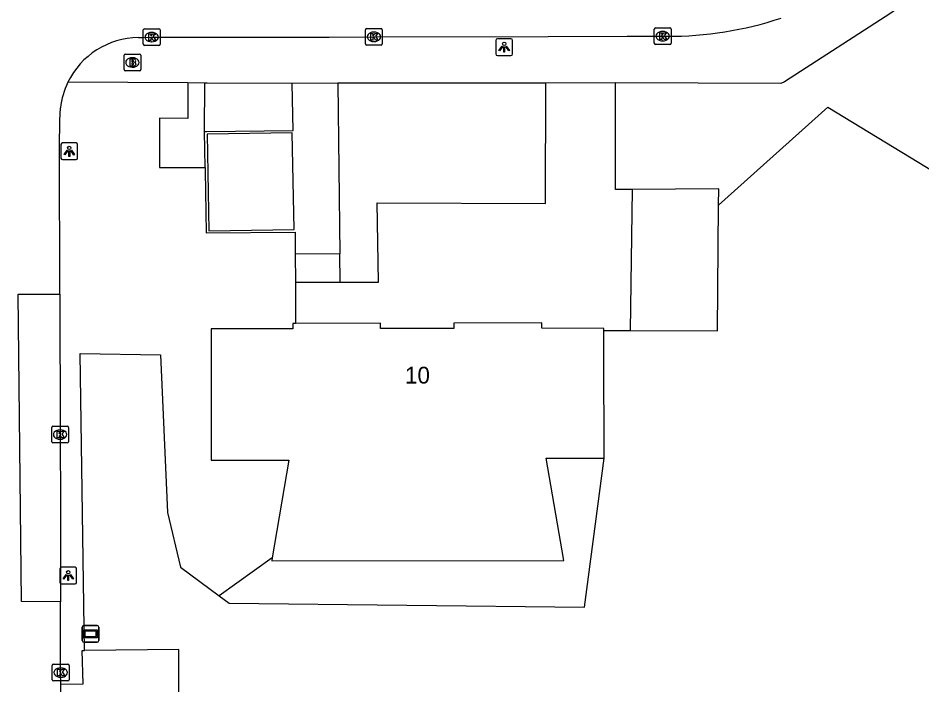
# Model space of a CAD drawing. Extents: x 161477 to 163040, y 383680 to 384868.
# Drawn here: x 162381.9 to 162435.8, y 384132.8 to 384172.5 of the extents above; entities that cross this region are included whole.
import ezdxf

# ---------------------------------------------------------------- set-up
doc = ezdxf.new("R2010")
doc.units = 0
for name, color, linetype in [('IMGEO_Brandkraan', 7, 'Continuous'), ('IMGEO_Groenvoorziening', 7, 'Continuous'), ('IMGEO_Kolk', 7, 'Continuous'), ('IMGEO_Lichtpunt', 7, 'Continuous'), ('IMGEO_Pand', 7, 'Continuous'), ('IMGEO_Pand_nummerreeks', 7, 'Continuous'), ('IMGEO_Parkeervlak_open', 7, 'Continuous'), ('IMGEO_Rijbaan_lokaal_open', 7, 'Continuous'), ('IMGEO_Verklikker', 7, 'Continuous'), ('IMGEO_Voetpad_open', 7, 'Continuous')]:
    doc.layers.add(name, color=color, linetype=linetype)

msp = doc.modelspace()

# ---------------------------------------------------------------- linework, layer by layer
at = {"layer": 'IMGEO_Brandkraan'}
for p, q in [((162388.314, 384170.36), (162389.166, 384170.36)), ((162388.239, 384169.434), (162388.239, 384170.286)), ((162388.727, 384170.14), (162388.752, 384170.14)), ((162389.24, 384170.286), (162389.24, 384169.434)), ((162389.166, 384169.36), (162388.314, 384169.36)), ((162388.75, 384169.58), (162388.725, 384169.58))]:
    msp.add_line(p, q, dxfattribs=at)
for points in [[(162388.314, 384170.36), (162389.166, 384170.36)], [(162388.239, 384169.434), (162388.239, 384170.286)], [(162388.587, 384170.06), (162388.587, 384169.66), (162388.8, 384169.66)], [(162388.818, 384170.06), (162388.587, 384170.06)], [(162388.766, 384169.979), (162388.712, 384169.979), (162388.712, 384169.903)], [(162388.712, 384169.903), (162388.765, 384169.903)], [(162388.774, 384169.827), (162388.712, 384169.827), (162388.712, 384169.746)], [(162389.24, 384170.286), (162389.24, 384169.434)], [(162389.166, 384169.36), (162388.314, 384169.36)], [(162388.712, 384169.746), (162388.774, 384169.746)]]:
    msp.add_lwpolyline(points, dxfattribs=at)
for centre, radius, start, end in [((162388.316, 384170.284), 0.0765, 91.552, 178.448), ((162388.316, 384170.284), 0.0765, 91.552, 178.448), ((162389.164, 384170.284), 0.0765, 1.552, 88.448), ((162389.164, 384170.284), 0.0765, 1.552, 88.448), ((162388.767, 384169.941), 0.0379, 267.8285, 90.9355), ((162388.775, 384169.786), 0.0404, 269.8759, 90.5077), ((162388.822, 384169.915), 0.145, 59.4692, 91.5367), ((162388.847, 384169.962), 0.0922, 285.5137, 58.1501), ((162388.852, 384169.77), 0.105, 301.3115, 78.989), ((162388.316, 384169.436), 0.0765, 181.552, 268.448), ((162388.316, 384169.436), 0.0765, 181.552, 268.448), ((162388.806, 384169.911), 0.251, 268.6676, 293.5347), ((162389.164, 384169.436), 0.0765, 271.552, 358.448), ((162389.164, 384169.436), 0.0765, 271.552, 358.448)]:
    msp.add_arc(centre, radius, start, end, dxfattribs=at)
for centre, major_axis, ratio, start_param, end_param in [((162388.726, 384169.86), (-0.387, 0.002), 0.722429, 4.712389, 7.853982), ((162388.751, 384169.86), (-0.39, 0.002), 0.717154, 1.570796, 4.712389)]:
    msp.add_ellipse(centre, major_axis=major_axis, ratio=ratio, start_param=start_param, end_param=end_param, dxfattribs=at)
at = {"layer": 'IMGEO_Groenvoorziening'}
for points in [[(162423.686, 384161.363), (162430.2, 384167.193), (162450.329, 384154.952)], [(162385.887, 384134.817), (162385.626, 384152.513), (162390.407, 384152.435), (162390.839, 384143.031), (162391.599, 384139.791), (162393.903, 384138.082)], [(162393.903, 384138.082), (162394.498, 384137.641), (162415.691, 384137.403), (162416.87, 384146.287)], [(162397.075, 384140.334), (162393.903, 384138.082)]]:
    msp.add_lwpolyline(points, dxfattribs=at)
at = {"layer": 'IMGEO_Kolk'}
for p, q in [((162419.927, 384171.928), (162420.779, 384171.928)), ((162389.389, 384170.946), (162389.389, 384171.798)), ((162389.464, 384171.872), (162390.316, 384171.872)), ((162389.877, 384171.652), (162389.902, 384171.652)), ((162390.39, 384171.798), (162390.39, 384170.946)), ((162402.634, 384170.962), (162402.634, 384171.814)), ((162402.709, 384171.888), (162403.561, 384171.888)), ((162403.122, 384171.668), (162403.147, 384171.668)), ((162403.635, 384171.814), (162403.635, 384170.962)), ((162419.852, 384171.002), (162419.852, 384171.854)), ((162420.34, 384171.708), (162420.365, 384171.708)), ((162420.853, 384171.854), (162420.853, 384171.002)), ((162390.316, 384170.872), (162389.464, 384170.872)), ((162389.9, 384171.092), (162389.875, 384171.092)), ((162403.561, 384170.888), (162402.709, 384170.888)), ((162403.145, 384171.108), (162403.12, 384171.108)), ((162420.779, 384170.928), (162419.927, 384170.928)), ((162420.363, 384171.148), (162420.338, 384171.148)), ((162383.929, 384147.258), (162383.929, 384148.11)), ((162384.004, 384148.184), (162384.856, 384148.184)), ((162384.417, 384147.964), (162384.442, 384147.964)), ((162384.93, 384148.11), (162384.93, 384147.258)), ((162384.856, 384147.184), (162384.004, 384147.184)), ((162384.44, 384147.404), (162384.415, 384147.404)), ((162383.96, 384133.074), (162383.96, 384133.926)), ((162384.035, 384134), (162384.887, 384134)), ((162384.448, 384133.78), (162384.473, 384133.78)), ((162384.961, 384133.926), (162384.961, 384133.074)), ((162384.471, 384133.22), (162384.446, 384133.22)), ((162384.887, 384133), (162384.035, 384133))]:
    msp.add_line(p, q, dxfattribs=at)
for points in [[(162419.927, 384171.928), (162420.779, 384171.928)], [(162389.389, 384170.946), (162389.389, 384171.798)], [(162389.464, 384171.872), (162390.316, 384171.872)], [(162389.71, 384171.572), (162389.833, 384171.572), (162389.833, 384171.421), (162389.963, 384171.572), (162390.127, 384171.572), (162389.981, 384171.421), (162390.134, 384171.172), (162389.982, 384171.172), (162389.897, 384171.336), (162389.833, 384171.269), (162389.833, 384171.172), (162389.71, 384171.172), (162389.71, 384171.572)], [(162390.39, 384171.798), (162390.39, 384170.946)], [(162402.634, 384170.962), (162402.634, 384171.814)], [(162402.709, 384171.888), (162403.561, 384171.888)], [(162402.955, 384171.588), (162403.078, 384171.588), (162403.078, 384171.437), (162403.208, 384171.588), (162403.372, 384171.588), (162403.226, 384171.437), (162403.379, 384171.188), (162403.227, 384171.188), (162403.142, 384171.352), (162403.078, 384171.285), (162403.078, 384171.188), (162402.955, 384171.188), (162402.955, 384171.588)], [(162403.635, 384171.814), (162403.635, 384170.962)], [(162419.852, 384171.002), (162419.852, 384171.854)], [(162420.173, 384171.628), (162420.296, 384171.628), (162420.296, 384171.477), (162420.426, 384171.628), (162420.59, 384171.628), (162420.444, 384171.477), (162420.597, 384171.228), (162420.445, 384171.228), (162420.36, 384171.392), (162420.296, 384171.325), (162420.296, 384171.228), (162420.173, 384171.228), (162420.173, 384171.628)], [(162420.853, 384171.854), (162420.853, 384171.002)], [(162390.316, 384170.872), (162389.464, 384170.872)], [(162403.561, 384170.888), (162402.709, 384170.888)], [(162420.779, 384170.928), (162419.927, 384170.928)], [(162383.929, 384147.258), (162383.929, 384148.11)], [(162384.004, 384148.184), (162384.856, 384148.184)], [(162384.25, 384147.884), (162384.373, 384147.884), (162384.373, 384147.733), (162384.503, 384147.884), (162384.667, 384147.884), (162384.521, 384147.733), (162384.674, 384147.484), (162384.522, 384147.484), (162384.437, 384147.648), (162384.373, 384147.581), (162384.373, 384147.484), (162384.25, 384147.484), (162384.25, 384147.884)], [(162384.93, 384148.11), (162384.93, 384147.258)], [(162384.856, 384147.184), (162384.004, 384147.184)], [(162383.96, 384133.074), (162383.96, 384133.926)], [(162384.035, 384134), (162384.887, 384134)], [(162384.281, 384133.7), (162384.404, 384133.7), (162384.404, 384133.549), (162384.534, 384133.7), (162384.698, 384133.7), (162384.552, 384133.549), (162384.705, 384133.3), (162384.553, 384133.3), (162384.468, 384133.464), (162384.404, 384133.397), (162384.404, 384133.3), (162384.281, 384133.3), (162384.281, 384133.7)], [(162384.961, 384133.926), (162384.961, 384133.074)], [(162384.887, 384133), (162384.035, 384133)]]:
    msp.add_lwpolyline(points, dxfattribs=at)
for centre, start, end in [((162419.929, 384171.852), 91.552, 178.448), ((162419.929, 384171.852), 91.552, 178.448), ((162420.777, 384171.852), 1.552, 88.448), ((162420.777, 384171.852), 1.552, 88.448), ((162389.466, 384171.796), 91.552, 178.448), ((162389.466, 384171.796), 91.552, 178.448), ((162390.314, 384171.796), 1.552, 88.448), ((162390.314, 384171.796), 1.552, 88.448), ((162402.711, 384171.812), 91.552, 178.448), ((162402.711, 384171.812), 91.552, 178.448), ((162403.559, 384171.812), 1.552, 88.448), ((162403.559, 384171.812), 1.552, 88.448), ((162389.466, 384170.948), 181.552, 268.448), ((162389.466, 384170.948), 181.552, 268.448), ((162390.314, 384170.948), 271.552, 358.448), ((162390.314, 384170.948), 271.552, 358.448), ((162402.711, 384170.964), 181.552, 268.448), ((162402.711, 384170.964), 181.552, 268.448), ((162403.559, 384170.964), 271.552, 358.448), ((162403.559, 384170.964), 271.552, 358.448), ((162419.929, 384171.004), 181.552, 268.448), ((162419.929, 384171.004), 181.552, 268.448), ((162420.777, 384171.004), 271.552, 358.448), ((162420.777, 384171.004), 271.552, 358.448), ((162384.006, 384148.108), 91.552, 178.448), ((162384.006, 384148.108), 91.552, 178.448), ((162384.854, 384148.108), 1.552, 88.448), ((162384.854, 384148.108), 1.552, 88.448), ((162384.006, 384147.26), 181.552, 268.448), ((162384.006, 384147.26), 181.552, 268.448), ((162384.854, 384147.26), 271.552, 358.448), ((162384.854, 384147.26), 271.552, 358.448), ((162384.037, 384133.924), 91.552, 178.448), ((162384.037, 384133.924), 91.552, 178.448), ((162384.885, 384133.924), 1.552, 88.448), ((162384.885, 384133.924), 1.552, 88.448), ((162384.037, 384133.076), 181.552, 268.448), ((162384.037, 384133.076), 181.552, 268.448), ((162384.885, 384133.076), 271.552, 358.448), ((162384.885, 384133.076), 271.552, 358.448)]:
    msp.add_arc(centre, 0.0765, start, end, dxfattribs=at)
for centre, major_axis, ratio, start_param, end_param in [((162389.876, 384171.372), (-0.387, 0.002), 0.722429, 4.712389, 7.853982), ((162389.901, 384171.372), (-0.39, 0.002), 0.717154, 1.570796, 4.712389), ((162403.121, 384171.388), (-0.387, 0.002), 0.722429, 4.712389, 7.853982), ((162403.146, 384171.388), (-0.39, 0.002), 0.717154, 1.570796, 4.712389), ((162420.339, 384171.428), (-0.387, 0.002), 0.722429, 4.712389, 7.853982), ((162420.364, 384171.428), (-0.39, 0.002), 0.717154, 1.570796, 4.712389), ((162384.416, 384147.684), (-0.387, 0.002), 0.722429, 4.712389, 7.853982), ((162384.441, 384147.684), (-0.39, 0.002), 0.717154, 1.570796, 4.712389), ((162384.447, 384133.5), (-0.387, 0.002), 0.722429, 4.712389, 7.853982), ((162384.472, 384133.5), (-0.39, 0.002), 0.717154, 1.570796, 4.712389)]:
    msp.add_ellipse(centre, major_axis=major_axis, ratio=ratio, start_param=start_param, end_param=end_param, dxfattribs=at)
at = {"layer": 'IMGEO_Lichtpunt'}
for p, q in [((162410.407, 384171.173), (162410.407, 384170.366)), ((162410.407, 384171.173), (162410.407, 384170.366)), ((162411.309, 384171.268), (162410.501, 384171.268)), ((162411.309, 384171.268), (162410.501, 384171.268)), ((162411.403, 384170.366), (162411.403, 384171.173)), ((162411.403, 384170.366), (162411.403, 384171.173)), ((162410.501, 384170.272), (162411.309, 384170.272)), ((162410.501, 384170.272), (162411.309, 384170.272)), ((162384.477, 384164.972), (162384.477, 384164.165)), ((162384.477, 384164.972), (162384.477, 384164.165)), ((162385.379, 384165.067), (162384.571, 384165.067)), ((162385.379, 384165.067), (162384.571, 384165.067)), ((162385.473, 384164.165), (162385.473, 384164.972)), ((162385.473, 384164.165), (162385.473, 384164.972)), ((162384.571, 384164.071), (162385.379, 384164.071)), ((162384.571, 384164.071), (162385.379, 384164.071)), ((162384.415, 384139.685), (162384.415, 384138.878)), ((162384.415, 384139.685), (162384.415, 384138.878)), ((162385.317, 384139.78), (162384.509, 384139.78)), ((162385.317, 384139.78), (162384.509, 384139.78)), ((162385.411, 384138.878), (162385.411, 384139.685)), ((162385.411, 384138.878), (162385.411, 384139.685)), ((162384.509, 384138.784), (162385.317, 384138.784)), ((162384.509, 384138.784), (162385.317, 384138.784))]:
    msp.add_line(p, q, dxfattribs=at)
for points in [[(162410.781, 384170.837), (162410.82, 384170.809), (162410.632, 384170.547), (162410.594, 384170.574), (162410.781, 384170.837)], [(162410.883, 384170.789), (162410.93, 384170.789), (162410.93, 384170.467), (162410.883, 384170.467), (162410.883, 384170.789)], [(162410.993, 384170.809), (162411.031, 384170.836), (162411.218, 384170.574), (162411.179, 384170.546), (162410.993, 384170.809)], [(162384.851, 384164.636), (162384.89, 384164.608), (162384.702, 384164.346), (162384.664, 384164.373), (162384.851, 384164.636)], [(162384.953, 384164.588), (162385, 384164.588), (162385, 384164.266), (162384.953, 384164.266), (162384.953, 384164.588)], [(162385.063, 384164.608), (162385.101, 384164.635), (162385.288, 384164.373), (162385.249, 384164.345), (162385.063, 384164.608)], [(162384.789, 384139.349), (162384.828, 384139.321), (162384.64, 384139.059), (162384.602, 384139.086), (162384.789, 384139.349)], [(162384.891, 384139.301), (162384.938, 384139.301), (162384.938, 384138.979), (162384.891, 384138.979), (162384.891, 384139.301)], [(162385.001, 384139.321), (162385.039, 384139.348), (162385.226, 384139.086), (162385.187, 384139.058), (162385.001, 384139.321)]]:
    msp.add_lwpolyline(points, dxfattribs=at)
for centre in [(162410.906, 384170.971), (162384.976, 384164.77), (162384.914, 384139.483)]:
    msp.add_circle(centre, 0.0994, dxfattribs=at)
for centre, start, end in [((162410.501, 384171.173), 90, 180), ((162410.501, 384171.173), 90, 180), ((162411.309, 384171.173), 0, 90), ((162411.309, 384171.173), 0, 90), ((162410.501, 384170.366), 180, 270), ((162410.501, 384170.366), 180, 270), ((162411.309, 384170.366), 270, 0), ((162411.309, 384170.366), 270, 360), ((162384.571, 384164.972), 90, 180), ((162384.571, 384164.972), 90, 180), ((162385.379, 384164.972), 0, 90), ((162385.379, 384164.972), 0, 90), ((162384.571, 384164.165), 180, 270), ((162384.571, 384164.165), 180, 270), ((162385.379, 384164.165), 270, 0), ((162385.379, 384164.165), 270, 360), ((162384.509, 384139.685), 90, 180), ((162384.509, 384139.685), 90, 180), ((162385.317, 384139.685), 0, 90), ((162385.317, 384139.685), 0, 90), ((162384.509, 384138.878), 180, 270), ((162384.509, 384138.878), 180, 270), ((162385.317, 384138.878), 270, 0), ((162385.317, 384138.878), 270, 360)]:
    msp.add_arc(centre, 0.0946, start, end, dxfattribs=at)
at = {"layer": 'IMGEO_Pand'}
for points in [[(162393.304, 384159.832), (162398.375, 384159.908), (162398.265, 384165.669), (162393.194, 384165.593), (162393.304, 384159.832)], [(162398.47, 384154.313), (162398.309, 384154.313), (162398.31, 384153.993), (162393.431, 384153.979), (162393.433, 384146.157), (162398.073, 384146.158), (162397.075, 384140.334)], [(162416.837, 384153.891), (162416.837, 384154.001), (162413.142, 384154.028), (162413.141, 384154.348), (162407.9, 384154.328), (162407.901, 384154.008), (162403.537, 384154.004), (162403.536, 384154.324), (162398.47, 384154.313)], [(162416.87, 384146.287), (162416.843, 384152.651), (162416.837, 384153.891)], [(162397.075, 384140.334), (162397.045, 384140.16), (162414.456, 384140.188), (162413.41, 384146.272), (162416.87, 384146.287)]]:
    msp.add_lwpolyline(points, dxfattribs=at)
at = {"layer": 'IMGEO_Parkeervlak_open'}
for points in [[(162423.686, 384161.363), (162423.694, 384162.32), (162418.525, 384162.295)], [(162418.419, 384153.886), (162423.619, 384153.869), (162423.686, 384161.363)], [(162384.414, 384156.056), (162384.43, 384147.685), (162384.451, 384143.354), (162384.457, 384137.718)]]:
    msp.add_lwpolyline(points, dxfattribs=at)
at = {"layer": 'IMGEO_Rijbaan_lokaal_open'}
for points in [[(162389.098, 384171.347), (162389.404, 384171.346), (162389.89, 384171.373), (162398.224, 384171.366), (162400.467, 384171.373), (162403.135, 384171.389), (162413.531, 384171.412), (162418.228, 384171.418), (162420.603, 384171.425)], [(162384.414, 384156.056), (162384.398, 384164.831), (162384.403, 384166.394), (162384.445, 384167.157)], [(162384.457, 384137.718), (162382.117, 384137.738), (162381.922, 384156.051), (162384.414, 384156.056)], [(162384.469, 384132.803), (162384.461, 384133.501), (162384.457, 384137.718)], [(162384.6, 384128.793), (162384.628, 384129.15), (162384.508, 384129.159), (162384.469, 384132.803)]]:
    msp.add_lwpolyline(points, dxfattribs=at)
for centre, radius, start, end in [((162420.758, 384192.437), 21.013, 269.5763, 288.4545), ((162389.155, 384166.606), 4.741, 90.6899, 154.1008), ((162389.111, 384166.616), 4.697, 153.9752, 173.3886)]:
    msp.add_arc(centre, radius, start, end, dxfattribs=at)
at = {"layer": 'IMGEO_Verklikker'}
for p, q in [((162385.745, 384135.41), (162385.745, 384136.21)), ((162385.745, 384136.21), (162385.745, 384135.41)), ((162385.845, 384136.31), (162386.635, 384136.31)), ((162386.635, 384136.31), (162385.845, 384136.31)), ((162386.735, 384136.21), (162386.735, 384135.41)), ((162386.735, 384135.41), (162386.735, 384136.21)), ((162386.635, 384135.31), (162385.845, 384135.31)), ((162385.845, 384135.31), (162386.635, 384135.31))]:
    msp.add_line(p, q, dxfattribs=at)
for points in [[(162385.846, 384136.042), (162386.634, 384136.042), (162386.634, 384135.578), (162385.846, 384135.578), (162385.846, 384136.042)], [(162385.911, 384135.977), (162385.911, 384135.643), (162386.569, 384135.643), (162386.569, 384135.977), (162385.911, 384135.977)]]:
    msp.add_lwpolyline(points, dxfattribs=at)
for centre, start, end in [((162385.845, 384136.21), 90, 180), ((162385.845, 384136.21), 90, 180), ((162386.635, 384136.21), 0, 90), ((162386.635, 384136.21), 360, 90), ((162385.845, 384135.41), 180, 270), ((162385.845, 384135.41), 180, 270), ((162386.635, 384135.41), 270, 0), ((162386.635, 384135.41), 270, 0)]:
    msp.add_arc(centre, 0.1, start, end, dxfattribs=at)
at = {"layer": 'IMGEO_Voetpad_open'}
for points in [[(162450.124, 384184.889), (162445.853, 384184.856), (162443.223, 384183.696), (162442.771, 384183.496), (162442.35, 384183.237), (162441.966, 384182.925), (162441.628, 384182.565), (162441.34, 384182.163), (162440.284, 384180.151), (162439.621, 384179.004), (162438.897, 384177.895), (162438.113, 384176.828), (162437.271, 384175.805), (162436.375, 384174.83), (162435.621, 384174.093), (162434.815, 384173.414), (162433.962, 384172.795), (162427.613, 384168.697), (162427.405, 384168.602), (162417.548, 384168.644)], [(162392.041, 384168.641), (162384.89, 384168.677)], [(162392.041, 384168.641), (162392.045, 384166.517), (162390.35, 384166.539), (162390.35, 384163.602), (162393.071, 384163.594)], [(162393.053, 384168.636), (162392.041, 384168.641)], [(162393.039, 384165.738), (162393.053, 384168.636)], [(162393.039, 384165.738), (162393.151, 384165.739), (162398.326, 384165.8), (162398.262, 384168.611)], [(162398.262, 384168.611), (162393.189, 384168.635), (162393.053, 384168.636)], [(162400.977, 384168.63), (162398.262, 384168.611)], [(162413.383, 384168.63), (162400.977, 384168.63)], [(162400.977, 384168.63), (162401.097, 384158.446)], [(162401.12, 384156.771), (162403.406, 384156.777), (162403.34, 384161.501), (162413.359, 384161.455), (162413.383, 384168.63)], [(162417.548, 384168.644), (162413.383, 384168.63)], [(162418.525, 384162.295), (162417.538, 384162.29), (162417.548, 384168.644)], [(162393.071, 384163.594), (162393.039, 384165.738)], [(162393.071, 384163.594), (162393.074, 384163.402), (162393.13, 384159.707), (162398.444, 384159.741), (162398.45, 384158.429)], [(162418.525, 384162.295), (162418.419, 384153.886)], [(162401.097, 384158.446), (162398.45, 384158.429)], [(162401.12, 384156.771), (162401.097, 384158.446)], [(162398.45, 384158.429), (162398.463, 384156.769)], [(162398.463, 384156.769), (162401.12, 384156.771)], [(162398.463, 384156.769), (162398.47, 384154.313)], [(162416.837, 384153.891), (162417.087, 384153.89), (162418.419, 384153.886)], [(162384.469, 384132.803), (162385.801, 384132.825), (162385.747, 384134.815), (162385.887, 384134.817)], [(162384.6, 384128.793), (162385.81, 384128.801), (162385.81, 384127.045), (162391.505, 384127.045), (162391.505, 384134.881), (162385.887, 384134.817)]]:
    msp.add_lwpolyline(points, dxfattribs=at)

# ---------------------------------------------------------------- texts
at = {"layer": 'IMGEO_Pand_nummerreeks'}
msp.add_text('10', height=1, rotation=0.0516, dxfattribs=at).set_placement((162404.99, 384150.725))

doc.saveas('drawing.dxf')
